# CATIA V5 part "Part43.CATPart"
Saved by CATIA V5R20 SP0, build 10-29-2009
Part number: FA 042200-1
Revision: ANY
Definition: UNKNOWN
Nomenclature: FA 042200-1
Source: Unknown
Bounding box of the stored display mesh (mm): x 0.374 to 3.8, y -1.58 to 1.58, z -1.58 to 1.58
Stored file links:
  C:\Users\Utente\Desktop\IO LAVORO\3D X SITO CF\CUMSA\3D files FA\FA 042200\Part43.CATPart

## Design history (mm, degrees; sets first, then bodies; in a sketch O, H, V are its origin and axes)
Body1 "Cortar-Extruir2" (main body)
  Solid1: solid without history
